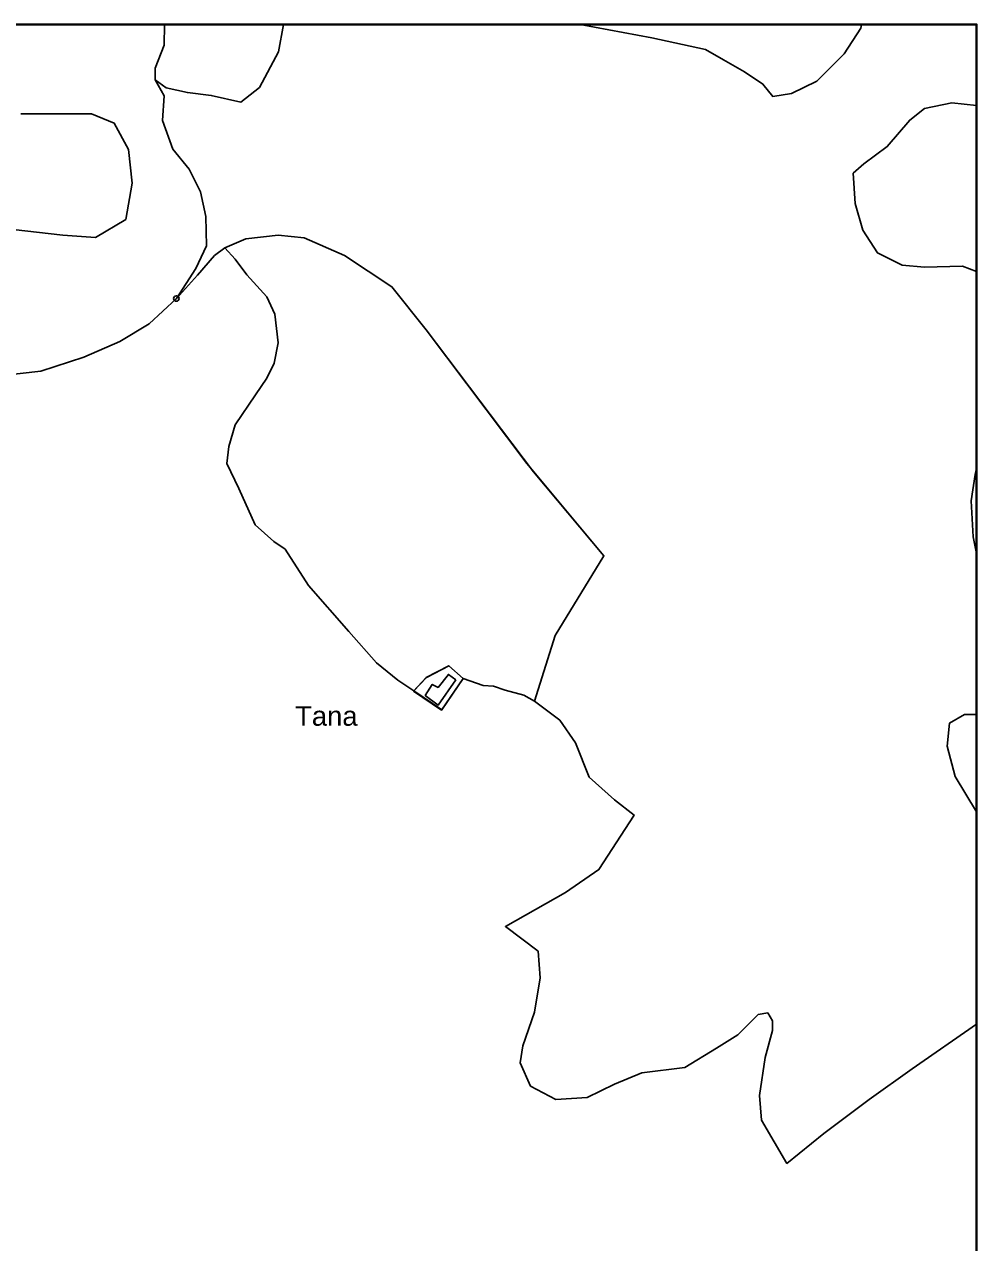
# Model space of a CAD drawing. Extents: x 652791 to 656927, y 889884 to 892405.
# Drawn here: x 656439 to 656927, y 891781 to 892405 of the extents above; entities that cross this region are included whole.
import ezdxf
from ezdxf.enums import TextEntityAlignment as Align

# ---------------------------------------------------------------- set-up
doc = ezdxf.new("R2010")
doc.units = 0
doc.header["$LTSCALE"] = 5.6
doc.header["$PDMODE"] = 32
doc.header["$PDSIZE"] = 2.8
for name, color, linetype, lineweight in [('36', 7, 'Continuous', 25), ('37', 7, 'Continuous', 25), ('4', 7, 'Continuous', 25), ('61', 7, 'Continuous', 35)]:
    doc.layers.add(name, color=color, linetype=linetype, lineweight=lineweight)
doc.layers.add('60', color=7, linetype='Continuous')

msp = doc.modelspace()

# ---------------------------------------------------------------- linework, layer by layer
at = {"layer": '36'}
for points in [[(656197.66, 892404.69), (656511.01, 892404.69), (656510.85, 892394.11), (656506.27, 892382.25), (656506.27, 892376.25)], [(656571.92, 892404.69), (656569.46, 892390.59), (656559.61, 892372.29), (656550.07, 892364.91), (656535, 892368.3), (656522.77, 892369.74), (656511.94, 892372.25), (656506.27, 892376.25)], [(656926.84, 892363.08), (656926.84, 892404.69), (656867.95, 892404.69), (656867.55, 892402.75), (656859.04, 892389.63), (656845.01, 892375.53), (656831.98, 892369.21), (656822.46, 892367.76), (656817.45, 892374.07), (656807.93, 892380.39), (656797.24, 892386.56), (656788.04, 892391.82), (656760.52, 892397.71), (656723.9, 892404.69), (656571.92, 892404.69)], [(656506.27, 892376.25), (656510.85, 892368.07), (656509.92, 892355.4), (656515.31, 892340.85), (656523.66, 892330.54), (656529.49, 892318.86), (656532.27, 892306.35), (656532.55, 892291.34), (656526.99, 892279.67), (656517.11, 892264.29), (656503.19, 892251.29), (656488.23, 892242.28), (656469.67, 892234.28), (656447.77, 892227.11), (656418.86, 892223.82), (656403.75, 892220.53), (656416.59, 892249.43), (656413.39, 892267.14), (656403.79, 892279.38)], [(656506.27, 892376.25), (656510.85, 892368.07), (656509.92, 892355.4), (656515.31, 892340.85), (656523.66, 892330.54), (656529.49, 892318.86), (656532.27, 892306.35), (656532.55, 892291.34), (656526.99, 892279.67), (656517.11, 892264.29), (656527.93, 892276.29), (656536.7, 892286.3), (656541.85, 892290.3), (656552.68, 892294.8), (656569.18, 892296.8), (656582.58, 892295.3), (656603.2, 892286.3), (656627.44, 892270.29), (656644.97, 892248.29), (656696.61, 892179.86), (656736.03, 892132.5), (656711.07, 892091.71), (656700.55, 892058.16), (656713.39, 892048.35), (656721.41, 892036.68), (656728.43, 892019.18), (656741.45, 892007.52), (656751.47, 891999.74), (656733.46, 891971.82), (656716.42, 891960.15), (656685.58, 891942.68), (656702.39, 891930.02), (656703.39, 891916.41), (656700.39, 891898.91), (656694.57, 891881.61), (656693.21, 891872.89), (656698.38, 891861), (656711.41, 891854.2), (656727.44, 891855.17), (656741.47, 891861.97)], [(656815, 891897.7), (656819.9, 891898.51), (656822.35, 891894.42), (656822.35, 891889.52), (656818.63, 891875.58), (656815.63, 891856.14), (656816.63, 891843.5), (656829.71, 891821.36), (656848.69, 891836.7), (656871.74, 891854.2), (656893.79, 891869.75), (656926.84, 891892.65), (656926.84, 892001.37), (656915.83, 892019.45), (656911.82, 892035), (656912.96, 892046.86), (656920.6, 892051.29), (656926.11, 892051.29), (656926.84, 892051.67), (656926.84, 892133.77), (656925.11, 892142.18), (656924.1, 892160.65), (656926.11, 892174.26), (656926.84, 892177.27), (656926.84, 892278.07), (656919.69, 892280.85), (656900.15, 892280.36), (656888.63, 892281.33), (656876.1, 892287.65), (656868.58, 892299.32), (656864.58, 892312.92), (656863.57, 892328.48), (656869.08, 892333.34), (656881.11, 892342.09), (656892.63, 892355.7), (656900.15, 892361.53), (656914.18, 892364.45), (656926.84, 892363.08)], [(656415.46, 892301.61), (656458.95, 892296.71), (656475.71, 892295.58), (656491.15, 892304.83), (656494.49, 892323.31), (656492.54, 892340.55), (656485.32, 892354.17), (656473.62, 892358.84), (656437.53, 892358.84)], [(656741.47, 891861.97), (656755.5, 891867.8), (656777.4, 891870.43), (656793.58, 891880.44), (656804.6, 891887.25), (656815, 891897.7)]]:
    msp.add_lwpolyline(points, dxfattribs=at)
at = {"layer": '37'}
for points in [[(656571.92, 892404.69), (656511.01, 892404.69), (656510.85, 892394.11), (656506.27, 892382.25), (656506.27, 892376.25), (656511.94, 892372.25), (656522.77, 892369.74), (656535, 892368.3)], [(656535, 892368.3), (656550.07, 892364.91), (656559.61, 892372.29), (656569.46, 892390.59), (656571.92, 892404.69)], [(656415.46, 892301.61), (656458.95, 892296.71), (656475.71, 892295.58), (656491.15, 892304.83), (656494.49, 892323.31), (656492.54, 892340.55), (656485.32, 892354.17), (656473.62, 892358.84), (656437.53, 892358.84)], [(656664, 892069.77), (656674.1, 892066.21), (656679.53, 892065.79), (656685.39, 892063.7), (656695.01, 892061.19), (656700.55, 892058.16), (656711.07, 892091.71), (656736.03, 892132.5), (656699.97, 892175.49), (656644.97, 892248.29), (656627.44, 892270.29), (656603.2, 892286.3), (656582.58, 892295.3), (656569.18, 892296.8), (656552.68, 892294.8), (656541.85, 892290.3)], [(656638.64, 892063.31), (656630.43, 892068.88), (656619.64, 892077.67), (656605.34, 892093.73), (656584.77, 892117.32), (656572.73, 892135.9), (656566.96, 892139.91), (656557.43, 892148.44), (656549.16, 892167.02), (656542.88, 892179.82), (656543.89, 892188.6), (656547.15, 892199.64), (656557.68, 892214.95), (656563.45, 892223.48), (656567.21, 892231.26), (656569.22, 892241.55), (656567.47, 892256.36), (656563.45, 892265.14), (656553.17, 892276.44), (656547.15, 892284.47), (656541.85, 892290.3), (656536.7, 892286.3), (656527.93, 892276.29), (656517.11, 892264.29)], [(656541.85, 892290.3), (656547.15, 892284.47), (656553.17, 892276.44), (656563.45, 892265.14), (656567.47, 892256.36), (656569.22, 892241.55), (656567.21, 892231.26), (656563.45, 892223.48), (656557.68, 892214.95)], [(656517.11, 892264.29), (656503.19, 892251.29), (656488.23, 892242.28), (656469.67, 892234.28), (656447.77, 892227.11), (656418.86, 892223.82), (656403.75, 892220.53)], [(656557.68, 892214.95), (656547.15, 892199.64), (656543.89, 892188.6), (656542.88, 892179.82), (656549.16, 892167.02), (656557.43, 892148.44), (656566.96, 892139.91), (656569.06, 892138.46), (656572.73, 892135.9), (656584.77, 892117.32), (656605.34, 892093.73)], [(656605.34, 892093.73), (656619.64, 892077.67), (656630.43, 892068.88), (656638.64, 892063.31), (656645.1, 892070.23), (656656.63, 892076.23), (656664, 892069.77)], [(656700.55, 892058.16), (656695.01, 892061.19), (656685.39, 892063.7), (656679.53, 892065.79), (656674.1, 892066.21), (656664, 892069.77), (656652.94, 892053.62), (656638.64, 892063.31)], [(656818.63, 891875.58), (656822.35, 891889.52), (656822.35, 891894.42), (656819.9, 891898.51), (656815, 891897.7), (656804.6, 891887.25), (656793.58, 891880.44), (656777.4, 891870.43), (656755.5, 891867.8), (656741.47, 891861.97), (656727.44, 891855.17), (656711.41, 891854.2), (656698.38, 891861), (656693.21, 891872.89), (656694.57, 891881.61), (656700.39, 891898.91), (656703.39, 891916.41), (656702.39, 891930.02), (656685.58, 891942.68), (656716.42, 891960.15), (656733.46, 891971.82), (656751.47, 891999.74), (656741.45, 892007.52), (656728.43, 892019.18), (656721.41, 892036.68), (656713.39, 892048.35), (656700.55, 892058.16)], [(656926.84, 891767.45), (656926.84, 891892.65), (656893.79, 891869.75), (656871.74, 891854.2), (656848.69, 891836.7), (656829.71, 891821.36), (656816.63, 891843.5), (656815.63, 891856.14), (656818.63, 891875.58)]]:
    msp.add_lwpolyline(points, dxfattribs=at)
for points in [[(656867.95, 892404.69), (656723.9, 892404.69), (656760.52, 892397.71), (656788.04, 892391.82), (656797.24, 892386.56), (656807.93, 892380.39), (656817.45, 892374.07), (656822.46, 892367.76), (656831.98, 892369.21), (656845.01, 892375.53), (656859.04, 892389.63), (656867.55, 892402.75)], [(656926.84, 892278.07), (656926.84, 892363.08), (656914.18, 892364.45), (656900.15, 892361.53), (656892.63, 892355.7), (656881.11, 892342.09), (656869.08, 892333.34), (656863.57, 892328.48), (656864.58, 892312.92), (656868.58, 892299.32), (656876.1, 892287.65), (656888.63, 892281.33), (656900.15, 892280.36), (656919.69, 892280.85)], [(656926.84, 892133.77), (656926.84, 892177.27), (656926.11, 892174.26), (656924.1, 892160.65), (656925.11, 892142.18)], [(656926.84, 892001.37), (656926.84, 892051.67), (656926.11, 892051.29), (656920.6, 892051.29), (656912.96, 892046.86), (656911.82, 892035), (656915.83, 892019.45)]]:
    msp.add_lwpolyline(points, close=True, dxfattribs=at)
msp.add_point((656517.11, 892264.29), dxfattribs=at)
at = {"layer": '4'}
for points in [[(656638.6, 892063.25), (656652.9, 892053.56), (656663.96, 892069.71), (656656.59, 892076.17), (656645.06, 892070.17)], [(656660.25, 892069.01), (656656.37, 892071.8), (656651.11, 892065.13), (656648.13, 892066.68), (656644.56, 892061.06), (656651.23, 892056.1)]]:
    msp.add_lwpolyline(points, close=True, dxfattribs=at)
at = {"layer": '61', "lineweight": 40}
msp.add_lwpolyline([(654894.04, 892404.68), (656926.84, 892404.68), (656926.84, 889884.41), (654894.04, 889884.41)], close=True, dxfattribs=at)

# ---------------------------------------------------------------- texts
at = {"layer": '60', "width": 1.05}
msp.add_text('Tana', height=10, dxfattribs=at).set_placement((656593.9, 892045.52), align=Align.CENTER)

doc.saveas('drawing.dxf')
